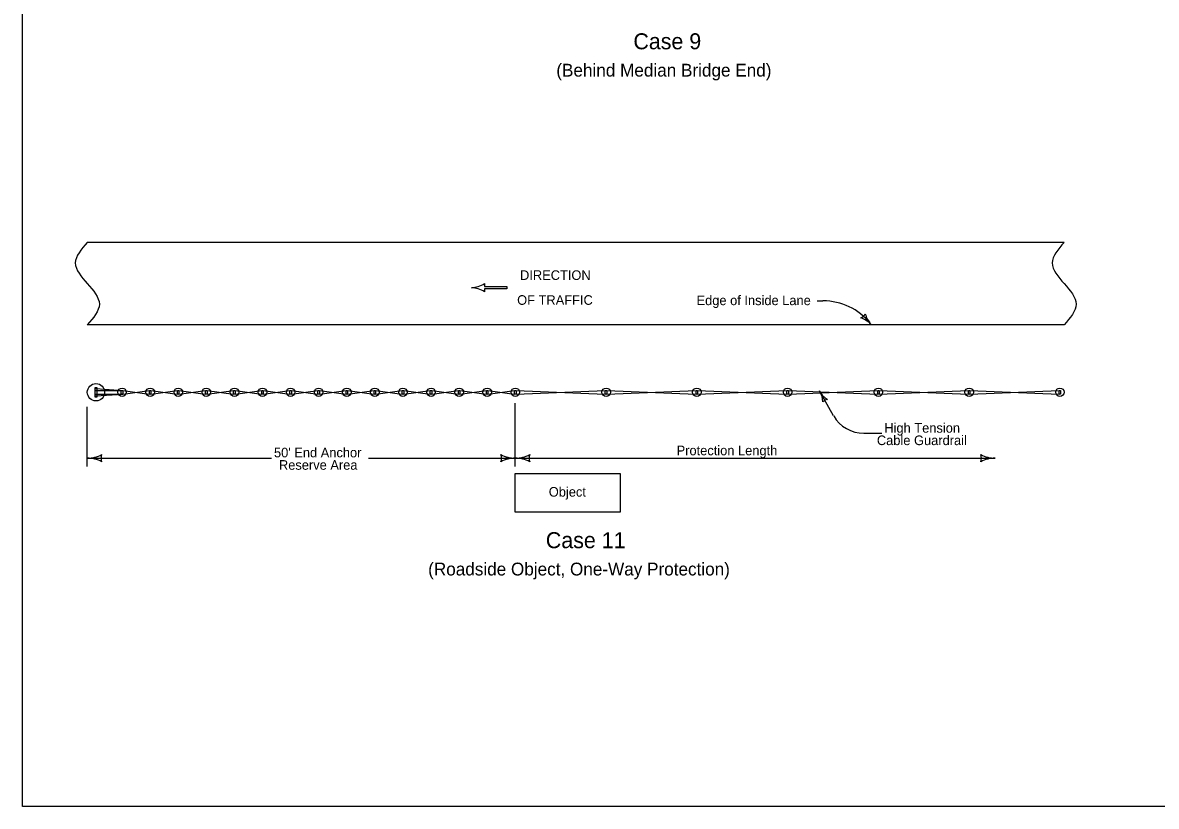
# Model space of a CAD drawing. Extents: x 10133 to 81668, y 7924 to 11018.
# Drawn here: x 13733 to 15149, y 7924 to 8903 of the extents above; entities that cross this region are included whole.
import ezdxf

# ---------------------------------------------------------------- set-up
doc = ezdxf.new("R2010")
doc.units = 0
for name, color, linetype in [('dsnCellElements', 7, 'Continuous'), ('DsnShtRevisedText', 7, 'Continuous'), ('dsnStdDimension', 7, 'Continuous'), ('Level 8', 7, 'Continuous'), ('SheetBorder', 7, 'Continuous')]:
    doc.layers.add(name, color=color, linetype=linetype)

msp = doc.modelspace()

# ---------------------------------------------------------------- linework, layer by layer
at = {"layer": 'dsnCellElements'}
for p, q in [((13824.1, 8446), (13857.6, 8443.6)), ((13824.1, 8443.6), (13855.8, 8443.6)), ((13857.6, 8443.6), (13890.8, 8439.1)), ((13857.6, 8439.1), (13890.8, 8443.6)), ((13892.7, 8443.6), (13925.9, 8439.1)), ((13892.7, 8439.1), (13925.9, 8443.6)), ((13927.8, 8443.6), (13961, 8439.1)), ((13927.8, 8439.1), (13961, 8443.6)), ((13962.9, 8443.6), (13996.1, 8439.1)), ((13962.9, 8439.1), (13996.1, 8443.6)), ((13998, 8443.6), (14031.2, 8439.1)), ((13998, 8439.1), (14031.2, 8443.6)), ((14033.1, 8443.6), (14066.3, 8439.1)), ((14033.1, 8439.1), (14066.3, 8443.6)), ((14068.2, 8439.1), (14101.4, 8443.6)), ((14068.2, 8443.6), (14101.4, 8439.1)), ((14103.2, 8443.6), (14136.5, 8439.1)), ((14103.2, 8439.1), (14136.5, 8443.6)), ((14138.4, 8443.6), (14171.5, 8439.1)), ((14138.4, 8439.1), (14171.5, 8443.6)), ((14173.4, 8443.6), (14206.7, 8439.1)), ((14173.4, 8439.1), (14206.7, 8443.6)), ((14208.6, 8443.6), (14241.7, 8439.1)), ((14208.6, 8439.1), (14241.7, 8443.6)), ((14243.6, 8443.6), (14276.9, 8439.1)), ((14243.6, 8439.1), (14276.9, 8443.6)), ((14278.7, 8443.6), (14311.9, 8439.1)), ((14278.7, 8439.1), (14311.9, 8443.6)), ((14313.8, 8443.6), (14347, 8439.1)), ((14313.8, 8439.1), (14347, 8443.6)), ((14348.9, 8443.6), (14460.4, 8439.1)), ((14348.9, 8439.1), (14460.4, 8443.6)), ((14462.3, 8443.6), (14573.9, 8439.1)), ((14462.3, 8439.1), (14573.9, 8443.6)), ((14575.7, 8443.6), (14687.3, 8439.1)), ((14575.7, 8439.1), (14687.3, 8443.6)), ((14689.1, 8443.6), (14800.7, 8439.1)), ((14689.1, 8439.1), (14800.7, 8443.6)), ((14802.5, 8443.6), (14914.1, 8439.1)), ((14802.5, 8439.1), (14914.1, 8443.6)), ((14915.9, 8443.6), (15027.5, 8439.1)), ((14915.9, 8439.1), (15027.5, 8443.6)), ((13824.1, 8439.1), (13855.8, 8439.1)), ((13824.1, 8436.8), (13857.6, 8439.1))]:
    msp.add_line(p, q, dxfattribs=at)
for points in [[(13822.9, 8435.4), (13822.9, 8447.4), (13825.3, 8447.4), (13825.3, 8435.4)], [(13855.7, 8439.1), (13855.7, 8443.6), (13857.6, 8443.6), (13857.6, 8439.1)], [(13890.8, 8439.1), (13890.8, 8443.6), (13892.7, 8443.6), (13892.7, 8439.1)], [(13925.9, 8439.1), (13925.9, 8443.6), (13927.8, 8443.6), (13927.8, 8439.1)], [(13961, 8439.1), (13961, 8443.6), (13962.9, 8443.6), (13962.9, 8439.1)], [(13996.1, 8439.1), (13996.1, 8443.6), (13998, 8443.6), (13998, 8439.1)], [(14031.2, 8439.1), (14031.2, 8443.6), (14033.1, 8443.6), (14033.1, 8439.1)], [(14066.3, 8439.1), (14066.3, 8443.6), (14068.2, 8443.6), (14068.2, 8439.1)], [(14101.4, 8439.1), (14101.4, 8443.6), (14103.2, 8443.6), (14103.2, 8439.1)], [(14136.5, 8439.1), (14136.5, 8443.6), (14138.4, 8443.6), (14138.4, 8439.1)], [(14171.5, 8439.1), (14171.5, 8443.6), (14173.4, 8443.6), (14173.4, 8439.1)], [(14206.7, 8439.1), (14206.7, 8443.6), (14208.6, 8443.6), (14208.6, 8439.1)], [(14241.7, 8439.1), (14241.7, 8443.6), (14243.6, 8443.6), (14243.6, 8439.1)], [(14276.9, 8439.1), (14276.9, 8443.6), (14278.7, 8443.6), (14278.7, 8439.1)], [(14311.9, 8439.1), (14311.9, 8443.6), (14313.8, 8443.6), (14313.8, 8439.1)], [(14347, 8439.1), (14347, 8443.6), (14348.9, 8443.6), (14348.9, 8439.1)], [(14347, 8439.1), (14347, 8443.6), (14348.9, 8443.6), (14348.9, 8439.1)], [(14460.4, 8439.1), (14460.4, 8443.6), (14462.3, 8443.6), (14462.3, 8439.1)], [(14460.4, 8439.1), (14460.4, 8443.6), (14462.3, 8443.6), (14462.3, 8439.1)], [(14573.9, 8439.1), (14573.9, 8443.6), (14575.7, 8443.6), (14575.7, 8439.1)], [(14573.9, 8439.1), (14573.9, 8443.6), (14575.7, 8443.6), (14575.7, 8439.1)], [(14687.3, 8439.1), (14687.3, 8443.6), (14689.1, 8443.6), (14689.1, 8439.1)], [(14687.3, 8439.1), (14687.3, 8443.6), (14689.1, 8443.6), (14689.1, 8439.1)], [(14800.7, 8439.1), (14800.7, 8443.6), (14802.5, 8443.6), (14802.5, 8439.1)], [(14800.7, 8439.1), (14800.7, 8443.6), (14802.5, 8443.6), (14802.5, 8439.1)], [(14914.1, 8439.1), (14914.1, 8443.6), (14915.9, 8443.6), (14915.9, 8439.1)], [(14914.1, 8439.1), (14914.1, 8443.6), (14915.9, 8443.6), (14915.9, 8439.1)], [(15027.5, 8439.1), (15027.5, 8443.6), (15029.3, 8443.6), (15029.3, 8439.1)]]:
    msp.add_lwpolyline(points, close=True, dxfattribs=at)
for centre, radius in [((13824.1, 8441.4), 10.8), ((13856.7, 8441.4), 5.32), ((13891.7, 8441.4), 5.32), ((13926.9, 8441.4), 5.32), ((13961.9, 8441.4), 5.32), ((13997.1, 8441.4), 5.32), ((14032.1, 8441.4), 5.32), ((14067.3, 8441.4), 5.32), ((14102.3, 8441.4), 5.32), ((14137.4, 8441.4), 5.32), ((14172.5, 8441.4), 5.32), ((14207.6, 8441.4), 5.32), ((14242.7, 8441.4), 5.32), ((14277.8, 8441.4), 5.32), ((14312.8, 8441.4), 5.32), ((14348, 8441.4), 5.32), ((14348, 8441.4), 5.32), ((14461.4, 8441.4), 5.32), ((14461.4, 8441.4), 5.32), ((14574.8, 8441.4), 5.32), ((14574.8, 8441.4), 5.32), ((14688.2, 8441.4), 5.32), ((14688.2, 8441.4), 5.32), ((14801.6, 8441.4), 5.32), ((14801.6, 8441.4), 5.32), ((14915, 8441.4), 5.32), ((14915, 8441.4), 5.32), ((15028.4, 8441.4), 5.32)]:
    msp.add_circle(centre, radius, dxfattribs=at)
at = {"layer": 'DsnShtRevisedText'}
for p, q in [((14293.3, 8572.1), (14293.3, 8572.1)), ((14309.5, 8577.2), (14309.5, 8573.6)), ((14309.5, 8573.6), (14337.5, 8573.6)), ((14337.5, 8570.6), (14309.5, 8570.6)), ((14309.5, 8570.6), (14309.5, 8567)), ((14337.5, 8573.6), (14337.5, 8570.6)), ((14724.9, 8555.6), (14732.3, 8555.6)), ((14745.7, 8411.8), (14728, 8443.1)), ((14348, 8348.5), (14348, 8427.8)), ((13813.3, 8348.5), (13813.3, 8423.2)), ((14783.3, 8390.2), (14805.8, 8390.2)), ((13813.3, 8359), (14043.4, 8359)), ((14164.4, 8359), (14390.9, 8359)), ((14390.9, 8359), (14558.9, 8359)), ((14558.9, 8359), (14947.5, 8359))]:
    msp.add_line(p, q, dxfattribs=at)
for centre, radius, start, end in [((14292, 8604.8), 32.7, 272.352, 302.382), ((14292, 8539.4), 32.7, 57.618, 87.648), ((14732.3, 8479.5), 76.2, 39.0106, 90), ((14774.3, 8545.6), 12.5, 295.2639, 330.7306), ((14769.2, 8503.7), 32.4, 42.9973, 71.0698), ((14816.5, 8547.9), 32.4, 194.9248, 222.9973), ((14705.1, 8428.4), 27.2, 2.1589, 30.2314), ((14752.1, 8455.7), 27.2, 210.2314, 238.3038), ((14740.1, 8422.3), 10.5, 102.498, 137.9647), ((14783.3, 8433.7), 43.5, 210.2243, 270), ((13813.3, 8397.3), 38.3, 270, 298.0725), ((13813.3, 8320.8), 38.3, 61.9275, 90), ((13845.3, 8359), 14.8, 162.2666, 197.7334), ((14315.9, 8359), 14.8, 342.2666, 17.7333), ((14348, 8397.3), 38.3, 241.9275, 270), ((14348, 8320.8), 38.3, 90, 118.0725), ((14348, 8397.3), 38.3, 270, 298.0725), ((14348, 8320.8), 38.3, 61.9275, 90), ((14380.1, 8359), 14.8, 162.2666, 197.7334), ((14915.4, 8359), 14.8, 342.2666, 17.7333), ((14947.5, 8397.3), 38.3, 241.9275, 270), ((14947.5, 8320.8), 38.3, 90, 118.0725)]:
    msp.add_arc(centre, radius, start, end, dxfattribs=at)
at = {"layer": 'dsnStdDimension'}
for p, q in [((15033.7, 8628.7), (13813.3, 8628.7)), ((15033.7, 8525.8), (13813.3, 8525.8))]:
    msp.add_line(p, q, dxfattribs=at)
msp.add_lwpolyline([(14348, 8340.1), (14478.9, 8340.1), (14478.9, 8291.6), (14348, 8291.6)], close=True, dxfattribs=at)
for points in [[(13813.3, 8628.7), (13798.3, 8603), (13813.3, 8577.2), (13828.3, 8551.5), (13813.3, 8525.8)], [(15033.7, 8628.7), (15018.7, 8603), (15033.7, 8577.2), (15048.7, 8551.5), (15033.7, 8525.8)]]:
    msp.add_spline(points, degree=3, dxfattribs=at)
at = {"layer": 'SheetBorder'}
msp.add_lwpolyline([(13732.5, 9944), (16867.5, 9944), (16867.5, 7924), (13732.5, 7924)], close=True, dxfattribs=at)

# ---------------------------------------------------------------- texts
at = {"layer": 'DsnShtRevisedText'}
for s, p in [('DIRECTION', (14353.9, 8581.8)), ('OF TRAFFIC', (14350.3, 8550.7)), ('Edge of Inside Lane', (14574.4, 8550.3)), ('High Tension', (14809, 8390.9)), ('Cable Guardrail', (14799.7, 8375.4)), ("50' End Anchor", (14046.5, 8360.1)), ('Protection Length', (14549.5, 8362.7)), ('Reserve Area', (14052.7, 8344.6)), ('Object', (14389.8, 8311))]:
    msp.add_text(s, height=12, dxfattribs=at).set_placement(p)
at = {"layer": 'Level 8'}
for s, height, p in [('Case 9', 20, (14495.5, 8870)), ('(Behind Median Bridge End)', 16, (14399.2, 8835.9)), ('Case 11', 20, (14386.1, 8246.6)), ('(Roadside Object, One-Way Protection)', 16, (14239.1, 8212.5))]:
    msp.add_text(s, height=height, dxfattribs=at).set_placement(p)

doc.saveas('drawing.dxf')
